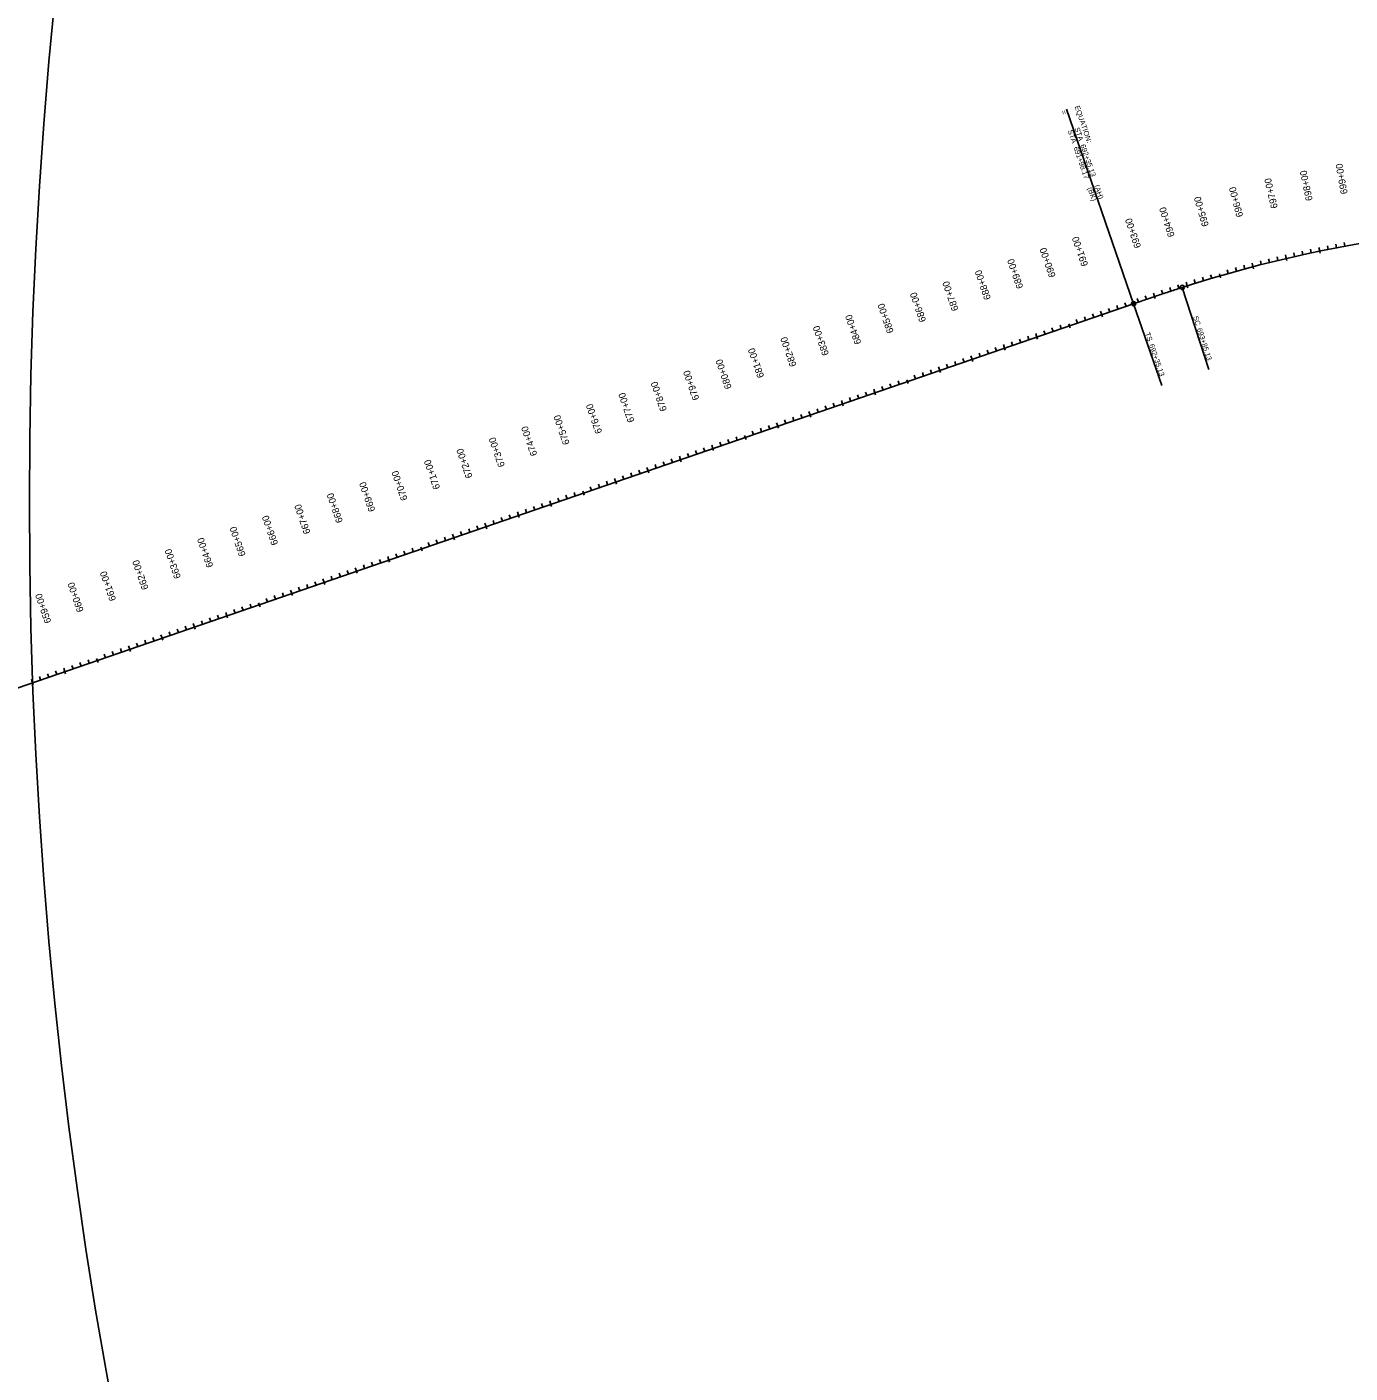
# Model space of a CAD drawing. Extents: x 22693007 to 22771804, y 6223023 to 6251673.
# Drawn here: x 22743147 to 22747008, y 6234805 to 6238732 of the extents above; entities that cross this region are included whole.
import ezdxf

# ---------------------------------------------------------------- set-up
doc = ezdxf.new("R2010")
doc.units = 0
for name, color, linetype in [('Default', 7, 'Continuous'), ('Draft_2', 7, 'Continuous'), ('NamedBoundary', 7, 'Continuous'), ('SheetBorder', 7, 'Continuous'), ('TextAlignment', 7, 'Continuous')]:
    doc.layers.add(name, color=color, linetype=linetype)

msp = doc.modelspace()

# ---------------------------------------------------------------- linework, layer by layer
at = {"layer": 'Default'}
msp.add_line((22740013.9, 6235734.9), (22746376.2, 6237924.7), dxfattribs=at)
msp.add_circle((22757478.8, 6237347.6), 14325, dxfattribs=at)
msp.add_arc((22747690.3, 6234337.1), 3819.7, 85.2926, 107.8679, dxfattribs=at)
msp.add_open_spline([(22746376.2, 6237924.7), (22746388, 6237928.8), (22746411.6, 6237936.9), (22746447.1, 6237949), (22746482.7, 6237961), (22746506.4, 6237968.8), (22746518.3, 6237972.6)], degree=3, dxfattribs=at)
at = {"layer": 'Draft_2'}
for p, q in [((22746821.7, 6238056.8), (22746819.2, 6238067.4)), ((22746919.3, 6238078.2), (22746917.1, 6238088.9)), ((22746724.6, 6238032.7), (22746721.8, 6238043.3)), ((22746532.5, 6237977.1), (22746529.2, 6237987.5)), ((22746626.5, 6238012.1), (22746629.9, 6238000.3)), ((22746437.5, 6237945.8), (22746434, 6237956.1)), ((22746283.4, 6237892.8), (22746279.8, 6237903.1)), ((22746186.8, 6237866), (22746190.8, 6237854.4)), ((22746094.2, 6237827.7), (22746090.7, 6237838)), ((22745999.7, 6237795.1), (22745996.1, 6237805.5)), ((22745905.1, 6237762.6), (22745901.6, 6237772.9)), ((22745810.6, 6237730), (22745807, 6237740.4)), ((22745621.5, 6237665), (22745617.9, 6237675.3)), ((22745714, 6237703.3), (22745718, 6237691.7)), ((22745526.9, 6237632.4), (22745523.4, 6237642.7)), ((22745432.4, 6237599.9), (22745428.8, 6237610.2)), ((22745337.8, 6237567.3), (22745334.2, 6237577.6)), ((22745148.7, 6237502.2), (22745145.1, 6237512.6)), ((22745241.2, 6237540.6), (22745245.2, 6237529)), ((22745054.1, 6237469.7), (22745050.6, 6237480)), ((22744959.6, 6237437.1), (22744956, 6237447.5)), ((22744865, 6237404.6), (22744861.5, 6237414.9)), ((22744768.5, 6237377.8), (22744772.5, 6237366.3)), ((22744581.3, 6237307), (22744577.8, 6237317.3)), ((22744675.9, 6237339.5), (22744672.4, 6237349.8)), ((22744486.8, 6237274.4), (22744483.2, 6237284.7)), ((22744392.2, 6237241.9), (22744388.7, 6237252.2)), ((22744295.7, 6237215.1), (22744299.7, 6237203.5)), ((22744108.6, 6237144.2), (22744105, 6237154.6)), ((22744203.1, 6237176.8), (22744199.6, 6237187.1)), ((22744014, 6237111.7), (22744010.5, 6237122)), ((22743919.5, 6237079.1), (22743915.9, 6237089.5)), ((22743822.9, 6237052.4), (22743826.9, 6237040.8)), ((22743730.3, 6237014.1), (22743726.8, 6237024.4)), ((22743541.2, 6236949), (22743537.7, 6236959.3)), ((22743635.8, 6236981.5), (22743632.2, 6236991.8)), ((22743446.7, 6236916.4), (22743443.1, 6236926.7)), ((22743350.1, 6236889.7), (22743354.1, 6236878.1)), ((22743257.6, 6236851.3), (22743254, 6236861.7)), ((22743163, 6236818.8), (22743159.5, 6236829.1))]:
    msp.add_line(p, q, dxfattribs=at)
at = {"layer": 'NamedBoundary'}
msp.add_line((22740013.9, 6235734.9), (22746376.2, 6237924.7), dxfattribs=at)
msp.add_arc((22747690.3, 6234337.1), 3819.7, 85.2926, 107.8679, dxfattribs=at)
msp.add_open_spline([(22746376.2, 6237924.7), (22746388, 6237928.8), (22746411.6, 6237936.9), (22746447.1, 6237949), (22746482.7, 6237961), (22746506.4, 6237968.8), (22746518.3, 6237972.6)], degree=3, dxfattribs=at)
at = {"layer": 'SheetBorder'}
for p, q in [((22746968.4, 6238088), (22746966.3, 6238098.7)), ((22746992.9, 6238092.6), (22746990.9, 6238103.4)), ((22746797.3, 6238051), (22746794.8, 6238061.6)), ((22746820.3, 6238062.7), (22746823, 6238050.8)), ((22746846, 6238062.4), (22746843.6, 6238073)), ((22746870.4, 6238067.8), (22746868.1, 6238078.5)), ((22746894.8, 6238073.1), (22746892.6, 6238083.8)), ((22746918.1, 6238084.2), (22746920.6, 6238072.2)), ((22746943.8, 6238083.2), (22746941.7, 6238093.9)), ((22746652.2, 6238013.1), (22746649.2, 6238023.6)), ((22746676.3, 6238019.8), (22746673.4, 6238030.3)), ((22746700.4, 6238026.3), (22746697.6, 6238036.9)), ((22746723, 6238038.7), (22746726.1, 6238026.8)), ((22746748.8, 6238039), (22746746.1, 6238049.6)), ((22746773, 6238045.1), (22746770.4, 6238055.7)), ((22746508.7, 6237969.5), (22746505.3, 6237979.9)), ((22746530.6, 6237983), (22746534.3, 6237971.3)), ((22746556.3, 6237984.6), (22746553.1, 6237995.1)), ((22746580.2, 6237992), (22746577.1, 6238002.4)), ((22746604.2, 6237999.2), (22746601.1, 6238009.6)), ((22746626.5, 6238012.1), (22746629.9, 6238000.3)), ((22746390.2, 6237929.6), (22746386.7, 6237939.9)), ((22746413.9, 6237937.7), (22746410.3, 6237948)), ((22746435.6, 6237951.6), (22746439.5, 6237940)), ((22746461.2, 6237953.8), (22746457.7, 6237964.1)), ((22746484.9, 6237961.7), (22746481.5, 6237972.1)), ((22746307, 6237900.9), (22746303.4, 6237911.2)), ((22746330.6, 6237909), (22746327.1, 6237919.4)), ((22746354.3, 6237917.2), (22746350.7, 6237927.5)), ((22746165.2, 6237852.1), (22746161.6, 6237862.4)), ((22746186.8, 6237866), (22746190.8, 6237854.4)), ((22746212.4, 6237868.4), (22746208.9, 6237878.7)), ((22746236.1, 6237876.5), (22746232.5, 6237886.8)), ((22746259.7, 6237884.6), (22746256.2, 6237895)), ((22746281.4, 6237898.6), (22746285.3, 6237887)), ((22746047, 6237811.4), (22746043.4, 6237821.7)), ((22746070.6, 6237819.5), (22746067.1, 6237829.9)), ((22746092.3, 6237833.5), (22746096.2, 6237821.9)), ((22746117.9, 6237835.8), (22746114.3, 6237846.1)), ((22746141.5, 6237844), (22746138, 6237854.3)), ((22745952.4, 6237778.9), (22745948.9, 6237789.2)), ((22745976, 6237787), (22745972.5, 6237797.3)), ((22745997.7, 6237800.9), (22746001.7, 6237789.3)), ((22746023.3, 6237803.3), (22746019.8, 6237813.6)), ((22745834.2, 6237738.2), (22745830.7, 6237748.5)), ((22745857.9, 6237746.3), (22745854.3, 6237756.6)), ((22745881.5, 6237754.5), (22745877.9, 6237764.8)), ((22745903.1, 6237768.4), (22745907.1, 6237756.8)), ((22745928.8, 6237770.7), (22745925.2, 6237781.1)), ((22745739.7, 6237705.6), (22745736.1, 6237716)), ((22745763.3, 6237713.8), (22745759.7, 6237724.1)), ((22745786.9, 6237721.9), (22745783.4, 6237732.2)), ((22745808.6, 6237735.8), (22745812.6, 6237724.3)), ((22745597.8, 6237656.8), (22745594.3, 6237667.1)), ((22745619.5, 6237670.7), (22745623.5, 6237659.2)), ((22745645.1, 6237673.1), (22745641.5, 6237683.4)), ((22745668.7, 6237681.2), (22745665.2, 6237691.6)), ((22745692.4, 6237689.4), (22745688.8, 6237699.7)), ((22745714, 6237703.3), (22745718, 6237691.7)), ((22745479.6, 6237616.1), (22745476.1, 6237626.5)), ((22745503.3, 6237624.3), (22745499.7, 6237634.6)), ((22745524.9, 6237638.2), (22745528.9, 6237626.6)), ((22745550.5, 6237640.5), (22745547, 6237650.9)), ((22745574.2, 6237648.7), (22745570.6, 6237659)), ((22745361.4, 6237575.5), (22745357.9, 6237585.8)), ((22745385.1, 6237583.6), (22745381.5, 6237593.9)), ((22745408.7, 6237591.7), (22745405.2, 6237602.1)), ((22745430.4, 6237605.7), (22745434.3, 6237594.1)), ((22745456, 6237608), (22745452.4, 6237618.3)), ((22745266.9, 6237542.9), (22745263.3, 6237553.2)), ((22745290.5, 6237551), (22745287, 6237561.4)), ((22745314.2, 6237559.2), (22745310.6, 6237569.5)), ((22745335.8, 6237573.1), (22745339.8, 6237561.5)), ((22745146.7, 6237508), (22745150.7, 6237496.4)), ((22745172.3, 6237510.4), (22745168.8, 6237520.7)), ((22745196, 6237518.5), (22745192.4, 6237528.8)), ((22745219.6, 6237526.6), (22745216, 6237537)), ((22745241.2, 6237540.6), (22745245.2, 6237529)), ((22745030.5, 6237461.5), (22745026.9, 6237471.9)), ((22745052.1, 6237475.5), (22745056.1, 6237463.9)), ((22745077.8, 6237477.8), (22745074.2, 6237488.1)), ((22745101.4, 6237486), (22745097.9, 6237496.3)), ((22745125, 6237494.1), (22745121.5, 6237504.4)), ((22744912.3, 6237420.9), (22744908.7, 6237431.2)), ((22744935.9, 6237429), (22744932.4, 6237439.3)), ((22744957.6, 6237442.9), (22744961.6, 6237431.4)), ((22744983.2, 6237445.3), (22744979.7, 6237455.6)), ((22745006.9, 6237453.4), (22745003.3, 6237463.7)), ((22744794.1, 6237380.2), (22744790.5, 6237390.5)), ((22744817.7, 6237388.3), (22744814.2, 6237398.6)), ((22744841.4, 6237396.5), (22744837.8, 6237406.8)), ((22744863, 6237410.4), (22744867, 6237398.8)), ((22744888.7, 6237412.7), (22744885.1, 6237423.1)), ((22744699.5, 6237347.6), (22744696, 6237358)), ((22744723.2, 6237355.8), (22744719.6, 6237366.1)), ((22744746.8, 6237363.9), (22744743.3, 6237374.2)), ((22744768.5, 6237377.8), (22744772.5, 6237366.3)), ((22744579.4, 6237312.7), (22744583.3, 6237301.2)), ((22744605, 6237315.1), (22744601.4, 6237325.4)), ((22744628.6, 6237323.2), (22744625.1, 6237333.6)), ((22744652.3, 6237331.4), (22744648.7, 6237341.7)), ((22744673.9, 6237345.3), (22744677.9, 6237333.7)), ((22744463.2, 6237266.3), (22744459.6, 6237276.6)), ((22744484.8, 6237280.2), (22744488.8, 6237268.6)), ((22744510.4, 6237282.5), (22744506.9, 6237292.9)), ((22744534.1, 6237290.7), (22744530.5, 6237301)), ((22744557.7, 6237298.8), (22744554.2, 6237309.1)), ((22744345, 6237225.6), (22744341.4, 6237235.9)), ((22744368.6, 6237233.7), (22744365, 6237244.1)), ((22744390.2, 6237247.7), (22744394.2, 6237236.1)), ((22744415.9, 6237250), (22744412.3, 6237260.3)), ((22744439.5, 6237258.1), (22744436, 6237268.5)), ((22744226.8, 6237184.9), (22744223.2, 6237195.2)), ((22744250.4, 6237193), (22744246.9, 6237203.4)), ((22744274, 6237201.2), (22744270.5, 6237211.5)), ((22744295.7, 6237215.1), (22744299.7, 6237203.5)), ((22744321.3, 6237217.5), (22744317.8, 6237227.8)), ((22744132.2, 6237152.4), (22744128.7, 6237162.7)), ((22744155.8, 6237160.5), (22744152.3, 6237170.8)), ((22744179.5, 6237168.6), (22744175.9, 6237179)), ((22744201.1, 6237182.6), (22744205.1, 6237171)), ((22744012, 6237117.5), (22744016, 6237105.9)), ((22744037.7, 6237119.8), (22744034.1, 6237130.1)), ((22744061.3, 6237128), (22744057.7, 6237138.3)), ((22744084.9, 6237136.1), (22744081.4, 6237146.4)), ((22744106.6, 6237150), (22744110.6, 6237138.4)), ((22743895.8, 6237071), (22743892.3, 6237081.3)), ((22743917.5, 6237084.9), (22743921.5, 6237073.4)), ((22743943.1, 6237087.3), (22743939.5, 6237097.6)), ((22743966.7, 6237095.4), (22743963.2, 6237105.7)), ((22743990.4, 6237103.6), (22743986.8, 6237113.9)), ((22743777.6, 6237030.3), (22743774.1, 6237040.6)), ((22743801.3, 6237038.5), (22743797.7, 6237048.8)), ((22743822.9, 6237052.4), (22743826.9, 6237040.8)), ((22743848.5, 6237054.7), (22743845, 6237065.1)), ((22743872.2, 6237062.9), (22743868.6, 6237073.2)), ((22743659.4, 6236989.6), (22743655.9, 6237000)), ((22743683.1, 6236997.8), (22743679.5, 6237008.1)), ((22743706.7, 6237005.9), (22743703.2, 6237016.2)), ((22743728.4, 6237019.8), (22743732.3, 6237008.3)), ((22743754, 6237022.2), (22743750.4, 6237032.5)), ((22743564.9, 6236957.1), (22743561.3, 6236967.4)), ((22743588.5, 6236965.2), (22743585, 6236975.6)), ((22743612.2, 6236973.4), (22743608.6, 6236983.7)), ((22743633.8, 6236987.3), (22743637.8, 6236975.7)), ((22743423, 6236908.3), (22743419.5, 6236918.6)), ((22743444.7, 6236922.2), (22743448.7, 6236910.6)), ((22743470.3, 6236924.6), (22743466.8, 6236934.9)), ((22743494, 6236932.7), (22743490.4, 6236943)), ((22743517.6, 6236940.8), (22743514, 6236951.2)), ((22743539.2, 6236954.7), (22743543.2, 6236943.2)), ((22743328.5, 6236875.7), (22743324.9, 6236886.1)), ((22743350.1, 6236889.7), (22743354.1, 6236878.1)), ((22743375.8, 6236892), (22743372.2, 6236902.3)), ((22743399.4, 6236900.1), (22743395.8, 6236910.5)), ((22743210.3, 6236835.1), (22743206.7, 6236845.4)), ((22743233.9, 6236843.2), (22743230.4, 6236853.5)), ((22743255.6, 6236857.1), (22743259.6, 6236845.5)), ((22743281.2, 6236859.5), (22743277.7, 6236869.8)), ((22743304.8, 6236867.6), (22743301.3, 6236877.9)), ((22743161, 6236824.6), (22743165, 6236813)), ((22743186.7, 6236826.9), (22743183.1, 6236837.2))]:
    msp.add_line(p, q, dxfattribs=at)
at = {"layer": 'TextAlignment'}
for p, q in [((22746376.2, 6237924.7), (22746180.9, 6238492.1)), ((22746180.9, 6238492.1), (22746180.9, 6238492.1)), ((22746518.3, 6237972.6), (22746595.6, 6237732.8)), ((22746518.3, 6237972.6), (22746595.6, 6237732.8)), ((22746376.2, 6237924.7), (22746458.2, 6237686.4)), ((22746595.6, 6237732.8), (22746595.6, 6237732.8)), ((22746595.6, 6237732.8), (22746595.6, 6237732.8)), ((22746458.2, 6237686.4), (22746458.2, 6237686.4))]:
    msp.add_line(p, q, dxfattribs=at)
for centre, radius in [((22746518.3, 6237972.6), 6.24), ((22746518.3, 6237972.6), 6.24), ((22746376.2, 6237924.7), 6.24), ((22746376.2, 6237924.7), 5.34)]:
    msp.add_circle(centre, radius, dxfattribs=at)

# ---------------------------------------------------------------- texts
at = {"layer": 'Draft_2'}
for s, rotation, p in [('695+00', 106.1449, (22746596.1, 6238153.1)), ('690+00', 108.9929, (22746149.5, 6238005.3)), ('685+00', 108.9929, (22745676.7, 6237842.6)), ('680+00', 108.9929, (22745203.9, 6237679.9)), ('675+00', 108.9929, (22744731.1, 6237517.1)), ('670+00', 108.9929, (22744258.3, 6237354.4)), ('665+00', 108.9929, (22743785.6, 6237191.7)), ('660+00', 108.9929, (22743312.8, 6237029))]:
    msp.add_text(s, height=20.04, rotation=rotation, dxfattribs=at).set_placement(p)
at = {"layer": 'SheetBorder'}
for s, rotation, p in [('699+00', 100.1449, (22747001, 6238246.5)), ('698+00', 101.6449, (22746898.9, 6238227.2)), ('696+00', 104.6449, (22746696.3, 6238180.4)), ('697+00', 103.1449, (22746797.3, 6238205.1)), ('695+00', 106.1449, (22746596.1, 6238153.1)), ('694+00', 107.6449, (22746496.6, 6238123.1)), ('693+00', 108.7825, (22746398.7, 6238091)), ('691+00', 108.9929, (22746244, 6238037.9)), ('690+00', 108.9929, (22746149.5, 6238005.3)), ('688+00', 108.9929, (22745960.3, 6237940.2)), ('689+00', 108.9929, (22746054.9, 6237972.8)), ('687+00', 108.9929, (22745865.8, 6237907.7)), ('686+00', 108.9929, (22745771.2, 6237875.1)), ('685+00', 108.9929, (22745676.7, 6237842.6)), ('684+00', 108.9929, (22745582.1, 6237810)), ('682+00', 108.9929, (22745393, 6237745)), ('683+00', 108.9929, (22745487.6, 6237777.5)), ('681+00', 108.9929, (22745298.5, 6237712.4)), ('680+00', 108.9929, (22745203.9, 6237679.9)), ('679+00', 108.9929, (22745109.3, 6237647.3)), ('677+00', 108.9929, (22744920.2, 6237582.2)), ('678+00', 108.9929, (22745014.8, 6237614.8)), ('676+00', 108.9929, (22744825.7, 6237549.7)), ('675+00', 108.9929, (22744731.1, 6237517.1)), ('674+00', 108.9929, (22744636.6, 6237484.6)), ('673+00', 108.9929, (22744542, 6237452.1)), ('671+00', 108.9929, (22744352.9, 6237387)), ('672+00', 108.9929, (22744447.5, 6237419.5)), ('670+00', 108.9929, (22744258.3, 6237354.4)), ('669+00', 108.9929, (22744163.8, 6237321.9)), ('668+00', 108.9929, (22744069.2, 6237289.3)), ('667+00', 108.9929, (22743974.7, 6237256.8)), ('665+00', 108.9929, (22743785.6, 6237191.7)), ('666+00', 108.9929, (22743880.1, 6237224.2)), ('664+00', 108.9929, (22743691, 6237159.1)), ('663+00', 108.9929, (22743596.4, 6237126.6)), ('662+00', 108.9929, (22743501.9, 6237094.1)), ('661+00', 108.9929, (22743407.3, 6237061.5)), ('659+00', 108.9929, (22743218.2, 6236996.4)), ('660+00', 108.9929, (22743312.8, 6237029))]:
    msp.add_text(s, height=20.04, rotation=rotation, dxfattribs=at).set_placement(p)
at = {"layer": 'TextAlignment'}
for s, rotation, p in [('=', 288.9929, (22746164.2, 6238486.3)), ('EQUATION:', 288.9929, (22746203.9, 6238500)), ('STA ', 288.9929, (22746183.7, 6238429.6)), ('STA ', 288.9929, (22746203.6, 6238436.4)), ('691+98.17', 288.9929, (22746200.6, 6238380.4)), ('692+35.13', 288.9929, (22746220.5, 6238387.3)), ('(BK)', 288.9929, (22746241.4, 6238262)), ('(AH)', 288.9929, (22746261.3, 6238268.8)), ('SC', 287.8679, (22746549.5, 6237886.8)), ('SC', 287.8679, (22746549.5, 6237886.8)), ('TS', 288.9929, (22746409.3, 6237838.5)), ('693+85.13', 287.8679, (22746560.8, 6237851.5)), ('693+85.13', 287.8679, (22746560.8, 6237851.5)), ('692+35.13', 288.9929, (22746421.1, 6237804.5))]:
    msp.add_text(s, height=15, rotation=rotation, dxfattribs=at).set_placement(p)

doc.saveas('drawing.dxf')
